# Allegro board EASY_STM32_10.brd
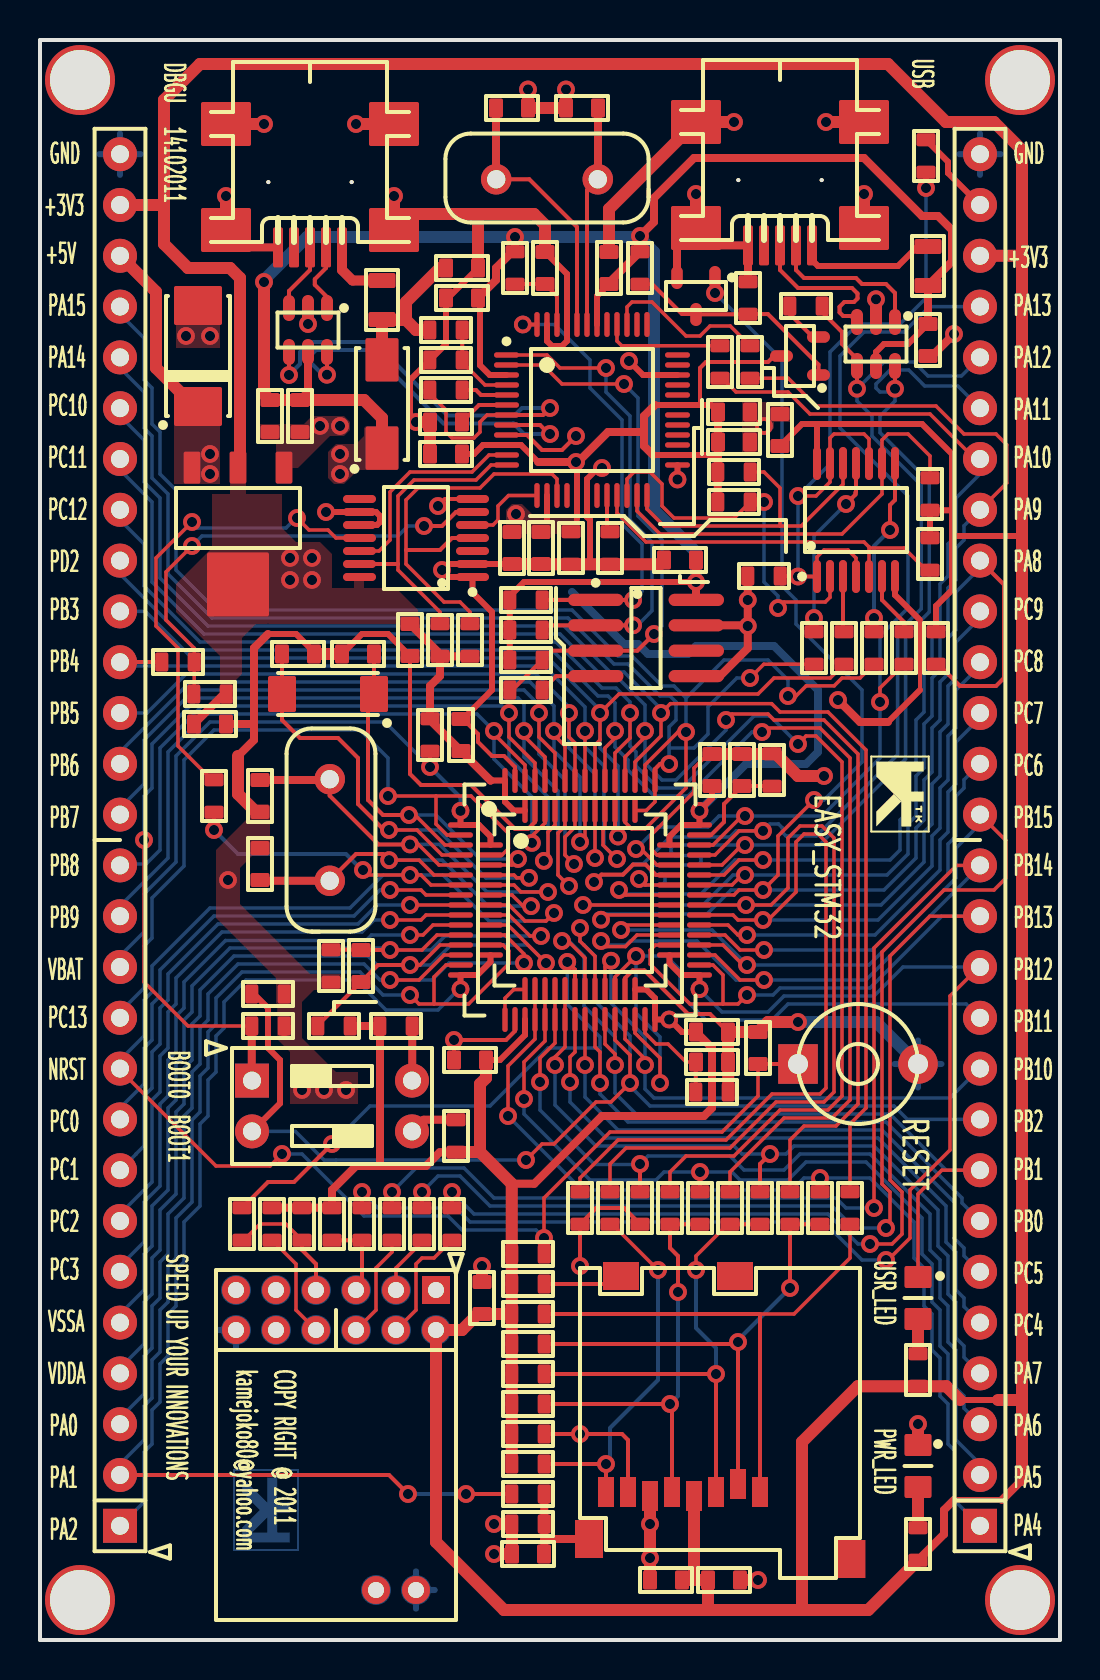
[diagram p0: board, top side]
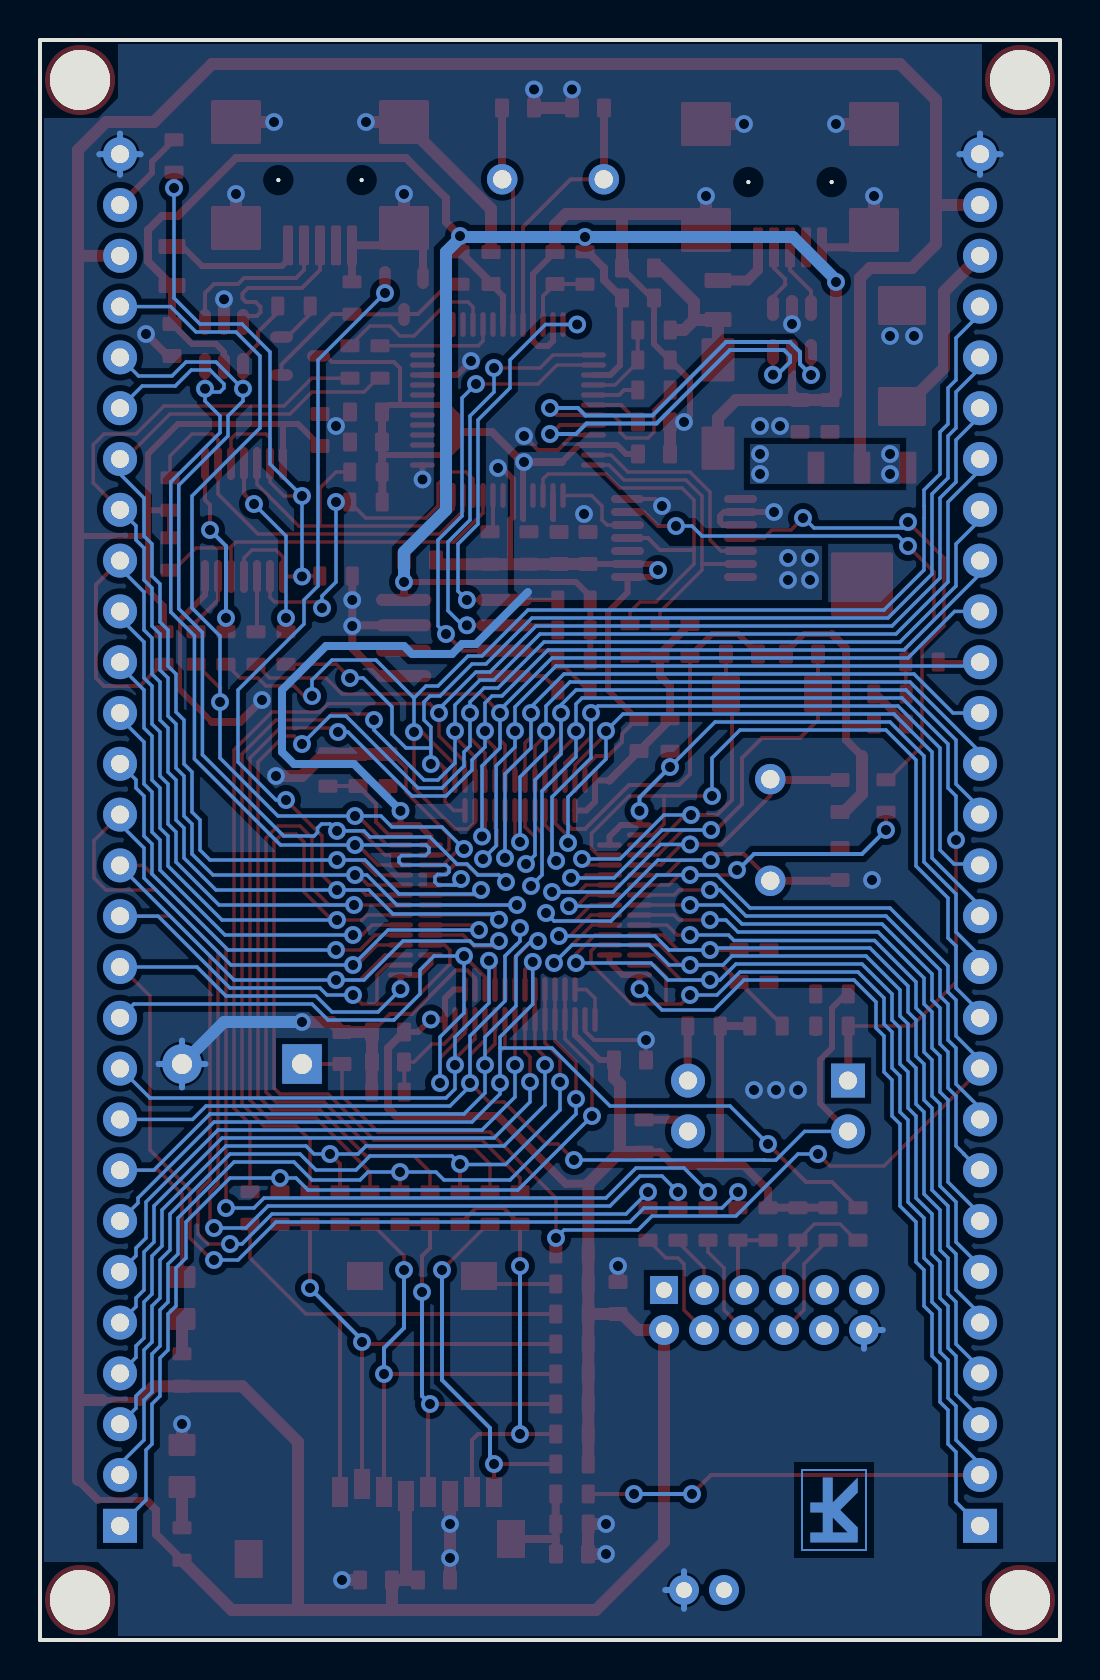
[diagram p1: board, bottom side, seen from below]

Outline 51 x 80 mm; copper layers: TOP, BOTTOM. Coordinates in mm from the lower left corner of the outline.
Outline path: 0,80 0,0 51,0 51,80 0,80

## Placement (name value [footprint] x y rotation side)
C1  22p  [CAP0603_B]  11 42.2 270 top
C2  22p  [CAP0603_B]  11 38.8 90 top
C3  15p  [CAP0603_B]  12.9 49.3 0 top
C4  15p  [CAP0603_B]  15.9 49.3 180 top
C5  100n  [CAP0603_B]  16.05 33.7 90 top
C6  100n  [CAP0603_B]  33.6 30.4 0 top
C7  100n  [CAP0603_B]  33.6 43.5 90 top
C8  100n  [CAP0603_B]  21.05 45.25 90 top
C9  100n  [CAP0603_B]  21.5 29 180 top
C10  10u  [CAP0603_B]  21.1 68.6 0 top
C11  100n  [CAP0603_B]  21.1 67.1 180 top
C12  100n  [CAP0603_B]  28.45 68.6 90 top
C13  10u  [CAP0603_B]  23.6 54.6 270 top
C14  100n  [CAP0603_B]  20.3 59.3 180 top
C15  100n  [CAP0603_B]  25.05 54.6 270 top
C16  100n  [CAP0603_B]  34.7 59.9 0 top
C17  100n  [CAP0603_B]  34.7 61.4 0 top
C18  100n  [CAP0603_B]  25.25 68.6 90 top
C19  100n  [CAP0603_B]  20.3 60.9 180 top
C20  22p  [CAP0603_B]  27.1 76.6 180 top
C21  22p  [CAP0603_B]  23.6 76.6 0 top
C22  100n  [CAP0603_B]  32 54 180 top
C23  220u  [CAP220UF]  7.9 64.2 90 top
C24  100n  [CAP0603_B]  11.5 61.2 270 top
C25  10u  [CAP0603_B]  8.5 45.8 0 top
C26  100n  [CAP0603_B]  44.4 65 270 top
C27  100n  [CAP0603_B]  33.6 28.9 0 top
C28  100n  [CAP0603_B]  35.1 43.5 90 top
C29  100n  [CAP0603_B]  13 61.2 270 top
C43  100n  [CAP0603_B]  31.3 3 180 top
C44  10u  [CAP0603_B]  34.2 3 0 top
C45  100n  [CAP0603_B]  37 60.5 90 top
C46  100n  [CAP0603_B]  18.5 50 270 top
C47  100n  [CAP0603_B]  24.4 4.3 180 top
C48  100n  [CAP0603_B]  35.9 29.6 90 top
C49  100n  [CAP0603_B]  22.1 17.1 90 top
D1  LED  [LEDC2012X120M]  43.9 8.7 270 top
D2  1N5819  [SS14]  17.1 61.8 90 top
D3  LED  [LEDC2012X120M]  43.9 17.1 270 top
J1  USB_MB  [HIROSE-US60-MB-5ST]  13.5 78.9 180 top
J2  USB_MB  [HIROSE-US60-MB-5ST]  37 79 180 top
J3  CON28  [CON28-1X28]  47 5.71 90 top
J4  CON28  [CON28-1X28]  4 5.71 90 top
L1  FB60R  [RES0805_B]  17.1 67 90 top
L2  FB60R  [RES0805_B]  44.4 68.7 90 top
NOREF  val  [unnamed]  49 78 0 top
NOREF#2  val  [unnamed]  2 78 0 top
NOREF#3  val  [unnamed]  49 2 0 top
NOREF#4  -  [#2]  51.55 -0.02 90 top
NOREF#5  val  [unnamed]  2 2 0 top
NOREF#6  -  [#2]  0.07 0.66 0 top
NOREF#7  -  [#2]  41.56 44.17 270 top
NOREF#8  -  [#2]  9.86 4.62 90 bottom
Q1  C1815  [SOT-23]  38 64.2 90 top
Q2  C1815  [SOT-23]  32.8 67.2 180 top
R1  0R  [RES0603_B]  19.5 45.25 90 top
R2  0R  [RES0603_B]  14.7 30.7 0 top
R3  0R  [RES0603_B]  14.55 33.7 270 top
R4  470R  [RES0603_B]  23.75 68.6 270 top
R5  4K7  [RES0603_B]  20.3 65.5 0 top
R6  10K  [RES0603_B]  20.3 64 180 top
R7  10K  [RES0603_B]  28.5 54.6 270 top
R8  10K  [RES0603_B]  24.3 49 0 top
R9  10K  [RES0603_B]  24.3 50.5 0 top
R10  10K  [RES0603_B]  24.3 52 0 top
R11  2K2  [RES0603_B]  24.3 47.5 0 top
R12  330R  [RES0603_B]  43.9 4.8 90 top
R13  1K5  [RES0603_B]  20.3 62.5 0 top
R14  100K  [RES0603_B]  26.55 54.6 270 top
R15  10K  [RES0603_B]  24.4 10.3 0 top
R16  10K  [RES0603_B]  24.4 13.3 0 top
R17  10K  [RES0603_B]  24.4 11.8 0 top
R18  10K  [RES0603_B]  24.4 14.8 0 top
R19  10K  [RES0603_B]  24.4 8.8 0 top
R20  10K  [RES0603_B]  24.4 16.3 0 top
R21  10K  [RES0603_B]  24.4 17.8 0 top
R22  1K  [RES0603_B]  24.4 5.8 180 top
R23  0R  [RES0603_B]  27 21.6 270 top
R24  0R  [RES0603_B]  34.5 21.6 270 top
R25  0R  [RES0603_B]  31.5 21.6 270 top
R26  0R  [RES0603_B]  37.5 21.6 270 top
R27  0R  [RES0603_B]  28.5 21.6 270 top
R28  0R  [RES0603_B]  40.5 21.6 270 top
R29  0R (DNP)  [RES0603_B]  30 21.6 90 top
R30  0R (DNP)  [RES0603_B]  36 21.6 90 top
R31  0R (DNP)  [RES0603_B]  33 21.6 90 top
R32  0R (DNP)  [RES0603_B]  39 21.6 90 top
R33  0R  [RES0603_B]  24.4 7.3 0 top
R34  39R  [RES0603_B]  34 63.9 270 top
R35  100R  [RES0603_B]  40.2 49.6 270 top
R36  100R  [RES0603_B]  43.2 49.6 270 top
R37  100R  [RES0603_B]  41.7 49.6 270 top
R38  100R  [RES0603_B]  38.7 49.6 270 top
R39  100K  [RES0603_B]  20 50 90 top
R40  100K  [RES0603_B]  21.5 50 90 top
R41  100R  [RES0603_B]  6.9 48.9 180 top
R42  100R  [RES0603_B]  8.7 42.2 270 top
R43  0R  [RES0603_B]  33.6 27.4 0 top
R44  10K  [RES0603_B]  30 68.6 270 top
R45  36K  [RES0603_B]  35.4 67.1 90 top
R46  1K5  [RES0603_B]  38.3 66.7 0 top
R47  47K  [RES0603_B]  44.8 49.6 270 top
R48  0R  [RES0603_B]  36.6 43.5 90 top
R49  10K  [RES0603_B]  24.4 19.3 0 top
R50  1K  [RES0603_B]  11.4 30.7 0 top
R51  1K  [RES0603_B]  11.4 32.3 0 top
R52  10K  [RES0603_B]  17.8 30.7 0 top
R53  10K  [RES0603_B]  20.8 25.2 90 top
R54  10K  [RES0603_B]  8.5 47.3 180 top
R55  10K  [RES0603_B]  34.7 56.9 0 top
R56  10K  [RES0603_B]  44.5 54.3 270 top
R57  10K  [RES0603_B]  44.5 57.3 90 top
R58  10K  [RES0603_B]  34.7 58.4 0 top
R59  39R  [RES0603_B]  35.5 63.9 270 top
R60  10K  [RES0603_B]  14.6 20.8 270 top
R61  0R  [RES0603_B]  16.1 20.8 270 top
R62  10K  [RES0603_B]  11.6 20.8 270 top
R63  10K  [RES0603_B]  13.1 20.8 270 top
R64  0R  [RES0603_B]  10.1 20.8 270 top
R65  0R  [RES0603_B]  19.1 20.8 270 top
R66  0R  [RES0603_B]  20.6 20.8 90 top
R67  0R  [RES0603_B]  17.6 20.8 90 top
R68  1K  [RES0603_B]  36.2 53.2 180 top
R69  10K  [RES0603_B]  44.3 74.2 270 top
R70  330R  [RES0603_B]  43.9 13.5 90 top
S1  BT  [BUTTON_RST_CIRCLE]  40.9 28.8 0 top
S2  SW DIP-2  [DIP_SWITCH_2]  14.6 26.7 270 top
U1  STM32F103RCT6  [LQFP64_MODIFIED]  27 37 0 top
U2  STM32F100  [LQFP48L_MODIFIED]  27 37 0 top
U3  FT2232D  [LQFP48L]  27.6 61.5 0 top
U4  AT93C46-10SI-2.7  [SOIC8S1JEDECM]  30.3 50.1 270 top
U5  74LVC125A  [TSOP65P640X120-14]  40.8 56 0 top
U6  74LVC125A  [TSOP65P640X120-14]  18.8 55.1 90 top
U7  LD1117-3V3  [SOT-223]  9.9 55.42 180 top
U8  RFM12  [RFM12-2X6]  19.8 17.5 180 top
U10  MICRO_SD  [MICRO_SD_PUSH]  41 18.6 180 top
U11  USBLC6-2P6  [SOT23-6L]  41.8 64.8 180 top
U12  USBLC6-2P6  [SOT23-6L]  13.4 65.5 180 top
Y1  8M  [XTAL_DIP]  14.49 37.96 90 top
Y2  32.768KHz  [ABS10]  14.4 47.3 180 top
Y3  6M  [XTAL_DIP]  27.89 73.04 180 top

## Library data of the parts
C1-C9 C24 C25 C27 C28 = C1005_0: User Part Number: pn; Tolerance: RichardLC
C10-C22 C26 C29 = CAP NP_0: User Part Number: pn; Tolerance: RichardLC
C23 = CAPACITOR POL: User Part Number: pn; Tolerance: RichardLC
C43-C49 = C1005_5: User Part Number: pn; Tolerance: RichardLC
D1 D3 = LED_0: User Part Number: pn; Tolerance: RichardLC
D2 = DIODE SCHOTTKY_1: User Part Number: pn; Tolerance: RichardLC
J1 J2 = CON9_2: User Part Number: pn; Tolerance: RichardLC
J3 J4 = CON26_0: User Part Number: pn; Tolerance: RichardLC
L1 L2 = INDUCTOR/SM_0: User Part Number: pn; Tolerance: RichardLC
NOREF NOREF#3 NOREF#5 = -: User Part Number: pn; Tolerance: RichardLC
NOREF#2 = -: Tolerance: RichardLC; User Part Number: pn
Q1 Q2 = 2N3904_0: User Part Number: pn; Tolerance: RichardLC
R1-R70 = R_0: User Part Number: pn; Tolerance: RichardLC
S1 = SW PUSHBUTTON_1: User Part Number: pn; Tolerance: RichardLC
S2 = SW DIP-2_1: User Part Number: pn; Tolerance: RichardLC
U1 = STM32F103RCT6_2: User Part Number: pn; Tolerance: RichardLC
U2 = STM32F100_1: User Part Number: pn; Tolerance: RichardLC
U3 = FT2232D_0: User Part Number: pn; Tolerance: RichardLC
U4 = 93C46_2: User Part Number: pn; Tolerance: RichardLC
U5 U6 = 74HC125/LCC_0: User Part Number: pn; Tolerance: RichardLC
U7 = LD1117: User Part Number: pn; Tolerance: RichardLC
U8 = RFM12: User Part Number: pn; Tolerance: RichardLC
U10 = MOLEX_uSD_0: User Part Number: pn; Tolerance: RichardLC
U11 U12 = USBLC6-2P6: User Part Number: pn; Tolerance: RichardLC
Y1 Y3 = ZTB: Tolerance: ***; User Part Number: ***
Y2 = ZTA: User Part Number: pn; Tolerance: RichardLC

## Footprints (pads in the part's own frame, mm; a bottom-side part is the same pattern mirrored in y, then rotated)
ABS10
  custom 0.35x0.35 smd: 1(-2.3,0) 2(2.3,0)
BUTTON_RST_CIRCLE
  rect 1.98x1.98 hole 1: 1(-3,0)
  round 1.98 hole 1: 2(3,0)
CAP220UF
  custom 0.487x0.487 smd: 1(-2.525,0) 2(2.525,0)
CAP0603_B
  custom 0.175x0.175 smd: 1(-0.8,0) 2(0.8,0)
CON28-1X28
  rect 1.7x1.7 hole 0.9: 1(0,0)
  round 1.7 hole 0.9: 2(2.54,0) 3(5.08,0) 4(7.62,0) 5(10.16,0) 6(12.7,0) 7(15.24,0) 8(17.78,0) 9(20.32,0) 10(22.86,0) 11(25.4,0) 12(27.94,0) 13(30.48,0) 14(33.02,0) 15(35.56,0) 16(38.1,0) 17(40.64,0) 18(43.18,0) 19(45.72,0) 20(48.26,0) 21(50.8,0) 22(53.34,0) 23(55.88,0) 24(58.42,0) 25(60.96,0) 26(63.5,0) 27(66.04,0) 28(68.58,0)
DIP_SWITCH_2
  rect 1.7x1.7 hole 0.9: 1(-1.27,-4)
  round 1.7 hole 0.9: 2(1.27,-4) 3(1.27,4) 4(-1.27,4)
HIROSE-US60-MB-5ST
  round 0.2 hole 0.9 unplated: (-2.083,6.005) (2.083,6.005)
  custom 0.125x0.125 smd: 1(-1.6,9.271) 2(-0.8,9.271) 3(0,9.271) 4(0.8,9.271) 5(1.6,9.271)
  custom 0.55x0.55 smd: 6(-4.2,3.1) 7(4.2,3.1) 8(-4.2,8.4) 9(4.2,8.4)
LEDC2012X120M
  custom 0.275x0.275 smd: A(1.05,0) C(-1.05,0)
LQFP48L
  oval 1.25x0.27 smd: 1(-4.275,2.75) 2(-4.275,2.25) 3(-4.275,1.75) 4(-4.275,1.25) 5(-4.275,0.75) 6(-4.275,0.25) 7(-4.275,-0.25) 8(-4.275,-0.75) 9(-4.275,-1.25) 10(-4.275,-1.75) 11(-4.275,-2.25) 12(-4.275,-2.75) 25(4.275,-2.75) 26(4.275,-2.25) 27(4.275,-1.75) 28(4.275,-1.25) 29(4.275,-0.75) 30(4.275,-0.25) 31(4.275,0.25) 32(4.275,0.75) 33(4.275,1.25) 34(4.275,1.75) 35(4.275,2.25) 36(4.275,2.75)
  oval 0.27x1.25 smd: 13(-2.75,-4.275) 14(-2.25,-4.275) 15(-1.75,-4.275) 16(-1.25,-4.275) 17(-0.75,-4.275) 18(-0.25,-4.275) 19(0.25,-4.275) 20(0.75,-4.275) 21(1.25,-4.275) 22(1.75,-4.275) 23(2.25,-4.275) 24(2.75,-4.275) 37(2.75,4.275) 38(2.25,4.275) 39(1.75,4.275) 40(1.25,4.275) 41(0.75,4.275) 42(0.25,4.275) 43(-0.25,4.275) 44(-0.75,4.275) 45(-1.25,4.275) 46(-1.75,4.275) 47(-2.25,4.275) 48(-2.75,4.275)
LQFP48L_MODIFIED
  oval 1.25x0.27 smd: 1(-4.475,2.75) 2(-4.475,2.25) 3(-4.475,1.75) 4(-4.475,1.25) 5(-4.475,0.75) 6(-4.475,0.25) 7(-4.475,-0.25) 8(-4.475,-0.75) 9(-4.475,-1.25) 10(-4.475,-1.75) 11(-4.475,-2.25) 12(-4.475,-2.75) 25(4.475,-2.75) 26(4.475,-2.25) 27(4.475,-1.75) 28(4.475,-1.25) 29(4.475,-0.75) 30(4.475,-0.25) 31(4.475,0.25) 32(4.475,0.75) 33(4.475,1.25) 34(4.475,1.75) 35(4.475,2.25) 36(4.475,2.75)
  oval 0.27x1.25 smd: 13(-2.75,-4.475) 14(-2.25,-4.475) 15(-1.75,-4.475) 16(-1.25,-4.475) 17(-0.75,-4.475) 18(-0.25,-4.475) 19(0.25,-4.475) 20(0.75,-4.475) 21(1.25,-4.475) 22(1.75,-4.475) 23(2.25,-4.475) 24(2.75,-4.475) 37(2.75,4.475) 38(2.25,4.475) 39(1.75,4.475) 40(1.25,4.475) 41(0.75,4.475) 42(0.25,4.475) 43(-0.25,4.475) 44(-0.75,4.475) 45(-1.25,4.475) 46(-1.75,4.475) 47(-2.25,4.475) 48(-2.75,4.475)
LQFP64_MODIFIED
  oval 1.25x0.27 smd: 1(-5.975,3.75) 2(-5.975,3.25) 3(-5.975,2.75) 4(-5.975,2.25) 5(-5.975,1.75) 6(-5.975,1.25) 7(-5.975,0.75) 8(-5.975,0.25) 9(-5.975,-0.25) 10(-5.975,-0.75) 11(-5.975,-1.25) 12(-5.975,-1.75) 13(-5.975,-2.25) 14(-5.975,-2.75) 15(-5.975,-3.25) 16(-5.975,-3.75) 33(5.975,-3.75) 34(5.975,-3.25) 35(5.975,-2.75) 36(5.975,-2.25) 37(5.975,-1.75) 38(5.975,-1.25) 39(5.975,-0.75) 40(5.975,-0.25) 41(5.975,0.25) 42(5.975,0.75) 43(5.975,1.25) 44(5.975,1.75) 45(5.975,2.25) 46(5.975,2.75) 47(5.975,3.25) 48(5.975,3.75)
  oval 0.27x1.25 smd: 17(-3.75,-5.975) 18(-3.25,-5.975) 19(-2.75,-5.975) 20(-2.25,-5.975) 21(-1.75,-5.975) 22(-1.25,-5.975) 23(-0.75,-5.975) 24(-0.25,-5.975) 25(0.25,-5.975) 26(0.75,-5.975) 27(1.25,-5.975) 28(1.75,-5.975) 29(2.25,-5.975) 30(2.75,-5.975) 31(3.25,-5.975) 32(3.75,-5.975) 49(3.75,5.975) 50(3.25,5.975) 51(2.75,5.975) 52(2.25,5.975) 53(1.75,5.975) 54(1.25,5.975) 55(0.75,5.975) 56(0.25,5.975) 57(-0.25,5.975) 58(-0.75,5.975) 59(-1.25,5.975) 60(-1.75,5.975) 61(-2.25,5.975) 62(-2.75,5.975) 63(-3.25,5.975) 64(-3.75,5.975)
MICRO_SD_PUSH
  rect 0.8x1.5 smd: 1(5,11.2) 2(6.1,10.8) 3(7.2,11.2) 4(8.3,11.4) 5(9.4,11.2) 6(10.5,11.4) 7(11.6,11.2) 8(12.7,11.2)
  rect 1.4x1.9 smd: G1(0.43,14.55) G2(13.55,13.55)
  rect 1.8x1.4 smd: S1(6.25,0.4) S2(11.95,0.4)
RES0603_B
  custom 0.163x0.163 smd: 1(-0.812,0) 2(0.812,0)
RES0805_B
  custom 0.188x0.188 smd: 1(-0.975,0) 2(0.975,0)
RFM12-2X6
  rect 1.4x1.4 hole 0.8: 1(0,0)
  round 1.4 hole 0.8: 2(0,2) 3(2,0) 4(2,2) 5(4,0) 6(4,2) 7(6,0) 8(6,2) 9(8,0) 10(8,2) 11(10,0) 12(10,2) 13(1,15) 14(3,15)
SOIC8S1JEDECM
  oval 0.61x2.77 smd: 1(-1.905,-2.515) 2(-0.635,-2.515) 3(0.635,-2.515) 4(1.905,-2.515) 5(1.905,2.515) 6(0.635,2.515) 7(-0.635,2.515) 8(-1.905,2.515)
SOT23-6L
  oval 0.6x1.3 smd: 1(-0.95,-1.1) 2(0,-1.1) 3(0.95,-1.1) 4(0.95,1.1) 5(0,1.1) 6(-0.95,1.1)
SOT-23
  oval 0.58x1.15 smd: 1(-0.95,-0.925) 2(0.95,-0.925) 3(0,0.925)
SOT-223
  custom 0.21x0.21 smd: 1(-2.3,-3.195) 2(0,-3.195) 3(2.3,-3.195)
  custom 0.775x0.775 smd: 4(0,2.645)
SS14
  custom 0.412x0.412 smd: A(2.21,0) C(-2.21,0)
TSOP65P640X120-14
  oval 0.4x1.65 smd: 1(-1.95,-2.825) 2(-1.3,-2.825) 3(-0.65,-2.825) 4(0,-2.825) 5(0.65,-2.825) 6(1.3,-2.825) 7(1.95,-2.825) 8(1.95,2.825) 9(1.3,2.825) 10(0.65,2.825) 11(0,2.825) 12(-0.65,2.825) 13(-1.3,2.825) 14(-1.95,2.825)
unnamed
  round 3.5 hole 3: 1(0,0)
XTAL_DIP
  round 1.524 hole 0.914: 1(0,0) 2(5.08,0)

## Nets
+3V3: C6.1 C7.1 C8.1 C9.1 C13.1 C14.1 C15.1 C16.1 C17.1 C25.1 C43.1 C44.1 C45.1 C46.1 C49.1 J3.26 J4.27 Q1.3(C) R1.2 R2.2 R12.1 R14.1 R15.1 R16.1 R17.1 R18.1 R19.1 R20.1 R21.1 R39.1 R40.1 R47.1 R49.1 R52.1 R53.1 R54.1 R55.1 R56.1 R57.1 R58.1 R60.1 R62.1 R63.1 R70.1 U1.19(VDD_4) U1.32(VDD_1) U1.48(VDD_2) U1.64(VDD_3) U2.24(VDD_1) U2.36(VDD_2) U2.48(VDD_3) U3.10(SI/WUA) U3.14(VCCIOA) U3.17(ADBUS6) U3.26(SI/WUB) U3.31(VCCIOB) U5.14(VCC) U6.14(VCC) U7.2(VOUT) U7.4(SH) U8.2(VDD) U10.4(VDD)
+5V: C11.1 C12.1 C22.1 C23.1 C24.1 C26.1 C29.1 D2.C J4.26 L2.1 R4.1 R8.1 R9.1 R10.1 R44.1 U3.3(VCC1) U3.42(VCC2) U4.8(VCC) U7.3(VIN) U11.5(VBUS) U12.5(VBUS)
GND: C1.2 C2.2 C3.2 C4.2 C6.2 C7.2 C8.2 C9.2 C10.2 C11.2 C12.2 C13.2 C14.2 C15.2 C16.2 C17.2 C18.2 C19.2 C20.2 C21.2 C22.2 C23.2 C24.2 C25.2 C26.2 C27.2 C28.2 C29.2 C43.2 C44.2 C45.2 C46.2 C47.2 C48.2 C49.2 D1.C J1.5(GND) J1.6(SH1) J1.7(SH2) J1.8(SH3) J1.9(SH4) J2.5(GND) J2.6(SH1) J2.7(SH2) J2.8(SH3) J2.9(SH4) J3.28 J4.28 Q2.2(E) R3.2 R6.2 R7.2 R14.2 R22.2 R43.2 R45.2 R48.2 R50.2 R51.2 R68.2 S1.2 U1.18(VSS_4) U1.63(VSS_3) U2.23(VSS_1) U2.35(VSS_2) U2.47(VSS_3) U3.9(GND1) U3.18(GND2) U3.25(GND3) U3.34(GND4) U3.45(AGND) U3.47(TEST) U4.5(GND) U4.7(NC) U5.7(GND) U6.1(O\E\1\) U6.2(A1) U6.7(GND) U6.9(A3) U6.10(O\E\3\) U7.1(GND) U8.12(GND1) U8.13(GND2) U10.6(VSS) U11.2(GND) U12.2(GND)
VBAT: J4.12 R1.1 U1.1(VBAT) U2.1(VBAT)
VDDA: C5.1 J4.4 R2.1 U1.13(VDDA) U2.9(VDDA)
VSSA: C5.2 J4.5 R3.1 U1.12(VSSA) U2.8(VSSA)
BOOT0: R50.1 S2.1 U1.60(BOOT0) U2.44(BOOT0)
EECK: R9.2 U3.1(EESK) U4.2(CLK)
EECS: R10.2 U3.48(EECS) U4.1(CS)
EEDA: R8.2 R11.1 U3.2(EEDATA) U4.3(DI)
JT_SRSTN: U3.16(ADBUS7)
JTAG_SELN: J3.27 R69.1
NRST: C48.1 J4.10 R42.2 R49.2 S1.1 U1.7(NRST) U2.7(NRST)
OSC32_IN: C4.1 U1.3(PC14/OSC32_IN) U2.3(PC14/OSC32_IN) Y2.1
OSC32_OUT: C3.1 U1.4(PC15/OSC32/OUT) U2.4(PC15/OSC32_OUT) Y2.2
OSC_IN: C1.1 U1.5(PD0/OSC_IN) U2.5(PD0/OSC_IN) Y1.2
OSC_OUT: C2.1 U1.6(PD1/OSC_OUT) U2.6(PD1/OSC_OUT) Y1.1
PA0: J4.3 U1.14(PA0-WKUP) U2.10(PA0/WKUP)
PA1: J4.2 R33.1 U1.15(PA1) U2.11(PA1)
PA2: J4.1 U1.16(PA2) U2.12(PA2)
PA3: U1.17(PA3) U2.13(PA3)
PA4: J3.1 R32.2 U1.20(PA4) U2.14(PA4)
PA5: J3.2 R31.2 U1.21(PA5) U2.15(PA5)
PA6: J3.3 R29.2 U1.22(PA6) U2.16(PA6)
PA7: J3.4 R30.2 U1.23(PA7) U2.17(PA7)
PA8: J3.20 Q2.1(B) R47.2 U1.41(PA8) U2.29(PA8)
PA9: J3.21 R59.2 U1.42(PA9) U2.30(PA9)
PA10: J3.22 R34.2 U1.43(PA10) U2.31(PA10)
PA11: J3.23 U1.44(PA11) U2.32(PA11) U11.6(IO1_2)
PA12: J3.24 R46.2 U1.45(PA12) U2.33(PA12) U11.4(IO2_2)
PA13: J3.25 R36.2 U1.46(PA13) U2.34(PA13)
PA14: J4.24 R38.2 U1.49(PA14) U2.37(PA14)
PA15: J4.25 R37.2 U1.50(PA15) U2.38(PA15)
PB0: J3.7 R64.1 U1.26(PB0) U2.18(PB0)
PB1: D3.C J3.8 U1.27(PB1) U2.19(PB1)
PB2: J3.9 R51.1 S2.2 U1.28(PB2/BOOT1) U2.20(PB2)
PB3: J4.19 R35.2 U1.55(PB3) U2.39(PB3)
PB4: J4.18 R41.2 U1.56(PB4) U2.40(PB4)
PB5: J4.17 U1.57(PB5) U2.41(PB5)
PB6: J4.16 U1.58(PB6) U2.42(PB6)
PB7: J4.15 U1.59(PB7) U2.43(PB7)
PB8: J4.14 U1.61(PB8) U2.45(PB8)
PB9: J4.13 U1.62(PB9) U2.46(PB9)
PB10: J3.10 U1.29(PB10) U2.21(PB10)
PB11: J3.11 U1.30(PB11) U2.22(PB11)
PB12: J3.12 R61.1 U1.33(PB12) U2.25(PB12)
PB13: J3.13 R66.2 U1.34(PB13) U2.26(PB13)
PB14: J3.14 R67.2 U1.35(PB14) U2.27(PB14)
PB15: J3.15 R65.1 U1.36(PB15) U2.28(PB15)
PC0: J4.9 U1.8(PC0)
PC1: J4.8 U1.9(PC1)
PC2: J4.7 U1.10(PC2)
PC3: J4.6 U1.11(PC3)
PC4: J3.5 U1.24(PC4)
PC5: J3.6 U1.25(PC5)
PC6: J3.16 U1.37(PC6)
PC7: J3.17 U1.38(PC7)
PC8: J3.18 R23.1 U1.39(PC8)
PC9: J3.19 R27.1 U1.40(PC9)
PC10: J4.23 R28.1 U1.51(PC10)
PC11: J4.22 R26.1 U1.52(PC11)
PC12: J4.21 R25.1 U1.53(PC12)
PC13: J4.11 U1.2(PC13/TAMPER/RTC) U2.2(PC13/TAMPER/RTC)
PD2: J4.20 R24.1 U1.54(PD2)
RXD: R59.1 U3.39(BDBUS1)
SRST: U3.11(ACBUS3) U6.12(A4)
SRST_OE: R39.2 U3.12(ACBUS2) U6.13(O\E\4\)
TRST: U3.13(ACBUS1) U6.5(A2)
TRST_OE: R40.2 U3.15(ACBUS0) U6.4(O\E\2\)
TXD: R34.1 U3.40(BDBUS0)
USB_CLK: R58.2 U3.24(ADBUS0) U5.12(A4)
USB_TDI: R57.2 U3.23(ADBUS1) U5.9(A3)
USB_TDO: R55.2 U3.22(ADBUS2) U5.2(A1)
USB_TMS: R56.2 U3.21(ADBUS3) U5.5(A2)
N50123: R13.1 U3.7(USBDP) U12.4(IO2_2)
N50127: C18.1 R4.2 U3.46(AVCC)
N50535: R7.1 U3.20(ADBUS4)
N50793: C20.1 U3.43(XTIN) Y3.1
N50801: C21.1 U3.44(XTOUT) Y3.2
N51029: C10.1 D2.A L1.1 R5.1
N51243: J1.1(VBUS) L1.2
N51319: R13.2 U3.5(R\S\T\O\U\T\)
N51343: U3.8(USBDM) U12.6(IO1_2)
N51347: R5.2 R6.1 U3.4(R\E\S\E\T\)
N51363: C19.1 U3.6(3V3OUT)
N51511: R11.2 U4.4(DO)
N51727: D1.A R12.2
N70187: R15.2 R23.2 R29.1 U10.7(DAT0/DO)
N70219: R17.2 R25.2 R31.1 U10.5(CLK)
N70227: R18.2 R26.2 R32.1 U10.2(CD/C\S\/DAT3)
N70305: R21.2 U10.S2
N70345: C47.1 R22.1 R33.2 U10.G2
N70603: R19.2 R27.2 U10.8(DAT1/RSV)
N14914218: R16.2 R24.2 R30.1 U10.3(CMD/DI)
N14919452: R35.1 U5.3(Y1)
N14919456: R36.1 U5.6(Y2)
N14919460: R37.1 U5.8(Y3)
N14919464: R38.1 U5.11(Y4)
N14919484: R68.1 R69.2 U5.1(O\E\1\) U5.4(O\E\2\) U5.10(O\E\3\) U5.13(O\E\4\)
N14919761: R20.2 R28.2 U10.1(DAT2/NC)
N14928576: R41.1 R54.2 U6.6(Y2)
N14928580: R42.1 U6.11(Y4)
N14948550: J2.1(VBUS) L2.2
N14948554: J2.2(DM) U11.1(IO1_1)
N14948558: J2.3(DP) U11.3(IO2_1)
N14952468: Q1.2(E) R46.1
N14953185: Q1.1(B) Q2.3(C) R44.2 R45.1
N14959571: J1.3(DP) U12.3(IO2_1)
N14961045: J1.2(DM) U12.1(IO1_1)
N14964930: C27.1 R43.1 U1.31(VSS_1)
N14964937: C28.1 R48.1 U1.47(VSS_2)
N14983071: R52.2 S2.4
N14983075: R53.2 S2.3
N14990127: R62.2 U8.8(FSK/DATA/NFFS)
N14990147: R66.1 U8.4(SCK)
N14990153: R67.1 U8.6(SDO)
N14990191: R65.2 U8.3(SDI)
N14990197: R60.2 R61.2 U8.5(NSEL)
N14990201: R63.2 R64.2 U8.7(NIR0)
N15001570: D3.A R70.2

Pads without a net: J1 4; J2 4; NOREF 1; NOREF#2 1; NOREF#3 1; NOREF#5 1; U3 19 27 28 29 30 32 33 35 36 37 38 41; U4 6; U6 3 8; U8 1 9 10 11 14; U10 G1 S1

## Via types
v1: diameter 0.889, hole 0.508, TOP to BOTTOM, 208 vias

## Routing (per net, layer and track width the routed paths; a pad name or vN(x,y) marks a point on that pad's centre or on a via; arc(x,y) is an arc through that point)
+3V3: length 386.6
  TOP w0.2: 49.09,69.21 49.1,69.2 ; 33,61.75 33,63.6 33.3,63.9 36.4,63.9 36.7,64.2 Q1.3 ; 26.8,56 26.85,56.05 ; 25.3,56 25.35,56.05 ; 45.59,56.49 45.6,56.5
  TOP w0.3: 26.9,58.9 v1(26.8,58.9) 26.85,58.85 U3.17 26.85,56.05 ; U2.36 31.48,40.17 32.05,40.75 U1.48 v1(32.98,41.46) 32.98,41.48 33.6,42.1 C7.1 ; C14.1 21.7,59.3 22.15,59.75 U3.10 24.05,59.75 24.9,58.9 ; U2.24 30.32,32.52 30.57,32.27 30.75,32.09 U1.32 v1(31.46,31.02) 31.48,31.02 32.1,30.4 C6.1 ; 49.1,55.2 45.6,55.2 ; 45.6,55.2 45.6,59.3 44.1,60.8 38.8,60.8 ; 45.6,55.2 45.6,52.5 44.8,51.7 R47.1 ; C9.1 23,29 24.25,30.25 U1.19 ; 38.8,60.8 38.1,60.8 C45.1 ; 38.8,60.8 38.85,60.75 U5.14 ; 25.35,56.05 U3.14 ; 30.75,61.75 U3.31 33.55,61.75 C17.1 ; 45.59,56.49 R57.1 R56.1 ; 30.65,59.25 U3.26 33.85,59.25 33.9,59.3 ; U2.48 23.69,41.48 23.25,41.91 U1.64 22.54,42.98 ; 48.1,7 45.7,7 ; 33.9,58.41 R58.1 ; 46,12 47.9,12
  TOP w0.4: 30.2,60.4 30.2,59.7 30.65,59.25 ; 30.2,60.4 30.2,61.2 30.75,61.75 ; 30.2,60.4 28.4,60.4 26.9,58.9 ; R12.1 45.2,5.29 45.2,6.5 45.7,7 ; R62.1 R63.1 R60.1 14.6,22.5 15.8,23.7 17,23.7 ; R40.1 R39.1 ; R39.1 20,48.2 19.5,47.7 R1.2 19.5,46 C8.1 22.52,42.98 22.54,42.98 ; R39.1 20,49.3 C46.1 ; 33.9,58.41 C16.1 C17.1 ; 49.1,8 48.1,7 ; C25.1 9.2,47.3 R54.1 ; 17,23.7 19.3,23.7 19.99,24.39 R53.1 ; 17,23.7 17,30.69 R52.1 R2.2 ; R58.1 R55.1 ; C6.1 33.6,29.6 33.6,26.6 33.2,26.2 28.1,26.2 24.71,22.81 23.59,22.81 ; 24.9,58.9 v1(26.8,58.9)
  TOP w0.6: 47.9,12 49.1,12 ; 49.1,12 49.1,74.5 47.7,75.9 45.3,75.9 42.4,78.8 8,78.8 6.2,77 6.2,71.7 ; 49.1,12 49.1,8 ; R20.1 R21.1 R49.1 23.59,22.81 22,24.4 ; R20.1 C49.1 21.9,16.3 21.1,15.5 U8.2 19.8,4.9 23.2,1.5 33.4,1.5 ; R20.1 R18.1 R16.1 R17.1 R15.1 R19.1 ; R12.1 41.41,1.5 38.1,1.5 ; C9.1 22.3,28.1 22,27.8 22,24.4 ; C43.1 32.7,3 ; 32.7,3 U10.4 ; 32.7,3 C44.1 33.4,1.5 ; 22,24.4 20.81,24.4 R53.1 ; 33.4,1.5 38.1,1.5 ; 46,12 45.31,12.69 R70.1 40.89,12.69 38.1,9.9 38.1,1.5 ; 6.2,71.7 6.15,71.75 J4.27 ; 6.2,71.7 6.2,69.8 7.4,68.6 9.5,68.6 10,68.1 10,58.72 U7.2 ; J3.26 49.09,69.21
  BOTTOM w0.4: 26.6,52.4 29.2,49.8 29.9,49.8 30.4,49.3 32.4,49.3 32.8,49.7 36.7,49.7 38.9,47.5 38.9,44.4 38.3,43.8 35.3,43.8 32.98,41.48 v1(32.98,41.46)
  vias: v1(12.5,54.1) v1(12.5,53) v1(13.6,54.1) v1(13.6,53) v1(23.8,56.3)
+5V: length 121
  TOP w0.2: C23.1 7.73,61.67
  TOP w0.3: C11.1 22,67 22,63.73 22.48,63.25 U3.3 ; v1(32.8,52.9) 24.2,52.9 23.49,52.19 R10.1 R9.1 R8.1 ; U3.42 27.85,67.2 C12.1 ; U11.5 41.8,64.4 42.2,64.8 43.4,64.8 C26.1
  TOP w0.4: C12.1 28.45,67.86 R44.1 ; 32.81,52.01 32.8,52.02 v1(32.8,52.9) C22.1 ; C11.1 22.8,68 22.8,68.6 23.61,69.41 R4.1 v1(23.75,70.15) ; v1(30,70.2) 30.7,70.9 30.7,72.1 32.7,74.1 41.2,74.1 44.1,71.2 44.9,71.2 45.6,70.5 45.6,68.92 L2.1 C26.1 ; C29.1 13.4,62.4 U12.5
  TOP w0.6: D2.C 17.1,61.1 16.2,62 C29.1 C24.1 11.2,62.3 v1(11.2,67.9) ; 7.73,61.67 5.8,63.6 5.8,67.41 J4.26 ; R44.1 v1(30,70.2)
  BOTTOM w0.2: 29.95,70.15 v1(30,70.2)
  BOTTOM w0.6: v1(32.8,52.9) 32.8,54.4 30.7,56.5 30.7,69.4 29.95,70.15 v1(23.75,70.15) 13.35,70.15 11.2,68 v1(11.2,67.9)
  vias: v1(8.5,59.3) v1(8.5,58.3) v1(15,59.3) v1(15,58.3)
GND: length 237.5
  TOP w0.175: C7.2 33.4,44.3 32.7,43.6 32.7,42.4 30.55,40.25 30.55,39.55 30.85,39.25 U2.35
  TOP w0.2: 44,51 44,47.5 ; U1.63 23.75,43.65 23.2,44.2 22.6,44.2 21.9,44.9 21.9,45.3 21.15,46.05 C8.2 ; U3.9 24.35,60.25 25.1,59.5 26.1,59.5 v1(26.8,60.2) ; C9.2 v1(20.7,30) 23.3,30 23.75,30.45 U1.18 ; v1(19.9,56.7) 20.25,57.05 21.62,57.05 ; C6.2 33.5,31.3 32.4,31.3 30.22,33.48 29.63,33.48 29.25,33.09 U2.23 ; U2.47 24.75,40.9 24.4,40.55 23.75,40.55 21.55,42.75 19.05,42.75 18.5,43.3 C46.2 ; 23.6,5.79 R22.2
  TOP w0.3: U3.25 v1(31.88,58.02) ; C10.2 20.4,67.1 C11.2 20.3,64.8 19.5,64 R6.2 19.49,63.99 18.5,63 18.5,61.2 v1(18.8,60.9) ; C4.2 16.1,50.3 17.4,50.3 C46.2 ; C13.2 20.4,53.8 v1(20.1,53.5) 20.45,53.15 21.62,53.15 21.62,52.38 22.6,51.4 22.6,47.5 21.15,46.05 ; 11.4,50.3 12.8,50.3 13.7,49.4 C3.2 ; v1(14.3,56.4) U6.9 16.8,56.4 17,56.2 17,55.9 16.85,55.75 U6.10 ; 44,51 42.75,52.25 U5.7 ; U3.47 25.35,64.95 25.6,64.7 26.1,64.7 26.35,64.95 U3.45 26.35,68.3 C18.2 ; v1(28.1,58.6) 27.9,58.6 27.35,58.05 U3.18 27.35,56.15 27.5,56 27.5,53.79 ; v1(29.45,63.95) 30.15,63.25 U3.34 ; 44,47.5 42.4,45.9
  TOP w0.4: C25.2 10.7,45.8 ; 10.7,45.8 10.7,49.6 11.4,50.3 ; 10.7,45.8 10.7,45 9.9,44.2 ; 32.81,50.73 35.35,50.73 v1(35.39,50.7) ; v1(35.39,50.7) v1(35.39,52) R68.2 ; v1(35.39,50.7) 35.39,49.59 33.99,48.2 32.81,48.2 ; J1.5 10.17,69.63 J1.9 ; R45.2 J2.5 33.67,69.73 J2.9 31.85,69.65 Q2.2 ; v1(39.9,47) 41,45.9 42.4,45.9 ; v1(45.7,65.3) 44.6,64.2 C26.2
  TOP w0.6: C43.2 v1(30.5,4.1) v1(30.5,5.8) U10.6 ; U11.2 v1(41.8,67.04) ; J2.6 v1(39.3,75.9) ; 9.9,44.2 9.9,42.3 10.8,41.4 C1.2 ; C12.2 28.45,71.55 J2.7 v1(34.7,75.9) ; C7.2 C28.2 36.59,44.3 R48.2 36.79,44.31 37.9,43.2 v1(39.2,43.2) ; J1.9 v1(9.3,72.2) ; 21.9,71.3 18.5,71.3 J1.8 v1(17.7,72.2) ; 21.9,71.3 C10.2 ; 21.9,71.3 24.7,71.3 25.25,70.75 C18.2 ; v1(18.8,60.9) C19.2 C14.2 ; v1(26.3,77.53) C20.2 C21.2 v1(24.4,77.53) ; U12.2 v1(13.4,65.8) ; D1.C v1(43.9,10.8) ; C22.2 30.99,53.79 R7.2 R14.2 25.06,53.79 C15.2 C13.2 ; J1.6 v1(15.8,75.8) ; v1(37.9,30.9) 36.4,30.9 C48.2 C6.2 C27.2 34.41,28.89 R43.2 ; 12.21,30.49 R50.2 ; J2.8 v1(41.2,72.3) ; J2.9 v1(32.8,72.3) ; C49.2 v1(22.1,18.7) ; J1.7 v1(11.2,75.8) ; v1(22.7,4.3) C47.2 23.6,5.79 ; C3.2 C4.2 ; R22.2 v1(22.7,5.8) ; C44.2 v1(35.9,3)
  BOTTOM w0.305: U8.13 18.8,3.43 ; U8.13 19.73,2.5 ; U8.13 18.8,1.57 ; 4,73.26 J4.28 ; J4.28 2.97,74.29 ; J4.28 5.03,74.29 ; J4.28 4,75.32 ; S1.2 43.9,29.97 ; S1.2 45.07,28.8 ; S1.2 43.9,27.63 ; S1.2 42.73,28.8 ; 45.97,74.29 J3.28 ; J3.28 47,73.26 ; J3.28 47,75.32 ; J3.28 48.03,74.29 ; 8.87,15.5 U8.12 9.8,14.57
  BOTTOM w0.6: v1(37.9,30.9) 41.8,30.9 S1.2
  vias: v1(7.3,65.2) v1(8.5,65.2) v1(9.4,38) v1(13.1,27.5) v1(14,60.7) v1(14.2,27.5) v1(15,60.7) v1(15.3,27.5) v1(36.2,60.7)
VBAT: length 32.5
  TOP w0.2: R1.1 v1(19.5,43.65)
  TOP w0.3: U2.1 22.52,40.17 21.95,40.75 U1.1 v1(21.02,41.46)
  BOTTOM w0.175: J4.12 4,34.2 5.2,35.4 5.2,37.3 6.8,38.9 6.8,44.2 8.5,45.9 17.25,45.9 v1(19.5,43.65)
  BOTTOM w0.2: v1(19.5,43.65) 21.02,42.12 v1(21.02,41.46)
VDDA: length 52.2
  TOP w0.175: v1(18.5,33.75) 19,33.75 20,34.75 U1.13 ; U2.9 23.4,35.75 v1(25.3,33.85)
  TOP w0.2: R2.1 13.89,30.74 C5.1 16.9,33.75 v1(18.5,33.75)
  BOTTOM w0.175: J4.4 4,13.6 5.2,14.8 5.2,16.9 5.6,17.3 5.6,19.1 6,19.5 6,21.5 6.8,22.3 6.8,26.4 7.2,26.8 7.2,28.6 7.6,29 7.6,30.8 8,31.2 8,32.5 9.7,34.2 16.4,34.2 16.85,33.75 v1(18.5,33.75) 19.55,33.75 20.55,34.75 24.4,34.75 v1(25.3,33.85)
VSSA: length 46.6
  TOP w0.175: U1.12 19.85,35.25 19.1,34.5 v1(17.5,34.5) ; U2.8 23.45,36.25 24.5,35.2 v1(25.05,35.2)
  TOP w0.2: v1(17.5,34.5) C5.2 16.04,34.51 R3.1
  BOTTOM w0.175: J4.5 4,16.3 5.2,17.5 5.2,19.3 5.6,19.7 5.6,21.7 6.4,22.5 6.4,26.6 6.8,27 6.8,28.8 7.2,29.2 7.2,31 7.6,31.4 7.6,32.7 9.5,34.6 17.4,34.6 v1(17.5,34.5) 19.55,34.5 20.25,35.2 v1(25.05,35.2)
BOOT0: length 57.9
  TOP w0.175: v1(24.2,45.45) 24.2,45.2 25.25,44.15 U1.60 ; v1(26.45,37.7) 25.9,38.25 25.9,40.35 26.25,40.7 U2.44 ; v1(5.2,40) 5.2,32.9 7.4,30.7 R50.1
  TOP w0.4: S2.1 10.59,27.98 R50.1
  BOTTOM w0.175: v1(5.2,40) 5.2,42.2 5.6,42.6 5.6,44.8 7.9,47.1 23.9,47.1 24.2,46.8 v1(24.2,45.45) 24.2,44.15 25.9,42.45 25.9,38.25 v1(26.45,37.7)
EECK: length 24.2
  TOP w0.175: U3.1 25.35,64.25 26,63.6 v1(28.3,63.6)
  TOP w0.2: R9.2 25.35,50.73 U4.2 v1(29.65,50.73)
  BOTTOM w0.175: v1(29.65,50.73) 29.87,50.73 30.6,51.47 30.6,54.9 29.5,56 29.5,61.2 28.3,62.4 v1(28.3,63.6)
EECS: length 25.3
  TOP w0.2: v1(29.66,52) R10.2 25.12,52.01 U4.1 ; U3.48 v1(24.14,65.78)
  BOTTOM w0.175: v1(24.14,65.78) 25.73,65.78 27.5,64 27.5,62.6 29.1,61 29.1,55.8 30.1,54.8 30.1,52.44 v1(29.66,52)
EEDA: length 28.1
  TOP w0.175: U3.2 25.15,63.75 26.1,62.8 v1(29.2,62.8)
  TOP w0.2: R11.1 23.61,47.5 R8.2 25.58,49.47 U4.3 29.87,49.47 v1(30.7,50.3)
  BOTTOM w0.175: v1(30.7,50.3) 31.1,50.7 31.1,55 29.9,56.2 29.9,62.1 v1(29.2,62.8)
JTAG_SELN: length 4.4
  TOP w0.3: J3.27 45.4,73.35 45.4,73.91 R69.1
NRST: length 91.4
  TOP w0.175: v1(16.15,38.5) 16.4,38.25 v1(18.5,38.25) 19.05,38.25 19.55,37.75 U1.7 ; C48.1 35.9,27.2 34.1,25.4 28.5,25.4 25.2,22.1 v1(25.2,20.1) 25.2,19.31 R49.2 ; J4.10 4,28.5 8.8,23.7 11.5,23.7 v1(12.1,24.3) ; v1(25.7,36.35) 25.3,35.95 24.25,35.95 23.45,36.75 U2.7
  TOP w0.2: C48.1 S1.1 ; R42.2 v1(8.7,40.5)
  BOTTOM w0.175: v1(25.7,36.35) 25.3,35.95 22.45,35.95 20.15,38.25 v1(18.5,38.25) 17.15,38.25 15.5,36.6 8.5,36.6 5.6,33.7 5.6,32.4 5.2,32 5.2,30.2 4,29 J4.10 ; v1(12.1,24.3) 13.1,24.3 16.2,21.2 20.4,21.2 21.1,20.5 24.8,20.5 v1(25.2,20.1)
  BOTTOM w0.2: v1(16.15,38.5) 16.1,38.5 15.3,39.3 9.9,39.3 v1(8.7,40.5)
OSC32_IN: length 20.8
  TOP w0.175: v1(18.45,41.25) 18.75,41.25 20.25,39.75 U1.3 ; U2.3 23.6,38.75 v1(23.9,39.05)
  TOP w0.2: v1(18.45,41.25) 17.15,41.25 16.4,42 16.4,47 Y2.1 C4.1
  BOTTOM w0.175: v1(23.9,39.05) 22,39.05 19.8,41.25 v1(18.45,41.25)
OSC32_OUT: length 26.3
  TOP w0.175: U2.4 23.7,38.25 23.84,38.11 v1(24.45,38.11) ; U1.4 20.1,39.25 18.85,40.5 v1(17.45,40.5)
  TOP w0.2: v1(17.45,40.5) 17.2,40.5 15.9,41.8 15.9,44.1 14.9,45.1 13,45.1 12.1,46 Y2.2 C3.1
  BOTTOM w0.175: v1(24.45,38.11) 24.44,38.1 22.3,38.1 19.9,40.5 v1(17.45,40.5)
OSC_IN: length 23.2
  TOP w0.175: v1(18.5,39.78) 18.92,39.78 19.95,38.75 U1.5 ; v1(25.4,37.4) 24.05,37.4 23.7,37.75 U2.5
  TOP w0.2: Y1.2 14.49,42.21 16.92,39.78 v1(18.5,39.78)
  TOP w0.4: Y1.2 14.45,43 C1.1
  BOTTOM w0.175: v1(18.5,39.78) 19.97,39.78 22.35,37.4 v1(25.4,37.4)
OSC_OUT: length 21.3
  TOP w0.175: U1.6 19.7,38.25 18.96,38.99 v1(17.46,38.99) ; v1(24.55,36.69) 24.16,36.69 23.6,37.25 U2.6
  TOP w0.2: v1(17.46,38.99) 17.15,39.3 15.8,39.3 14.49,37.99 Y1.1
  TOP w0.4: C2.1 11.04,37.96 Y1.1
  BOTTOM w0.175: v1(17.46,38.99) 20.11,38.99 22.41,36.69 v1(24.55,36.69)
PA0: length 47
  TOP w0.175: U1.14 20.2,34.25 18.95,33 v1(17.5,33) ; U2.10 23.25,35.25 24.2,34.3 v1(24.2,33.85)
  BOTTOM w0.175: v1(24.2,33.85) 20.45,33.85 19.6,33 v1(17.5,33) 17,33 16.2,33.8 9.9,33.8 8.4,32.3 8.4,31 8,30.6 8,28.8 7.6,28.4 7.6,26.6 7.2,26.2 7.2,22.1 6.4,21.3 6.4,19.3 6,18.9 6,17.1 5.6,16.7 5.6,14.6 5.2,14.2 5.2,12.3 4,11.1 J4.3
PA1: length 67.1
  TOP w0.175: U1.15 20.3,33.75 19.7,33.15 19.7,31.8 ; 19.7,31.8 21.43,31.8 23.45,33.82 23.45,34.45 23.15,34.75 U2.11 ; 19.7,31.8 18.95,31.8 v1(18.5,32.25)
  TOP w0.2: R33.1 v1(21.3,7.3) ; J4.2 17.45,8.25 v1(18.4,7.3)
  BOTTOM w0.175: v1(18.5,32.25) 17.15,32.25 16,33.4 10.1,33.4 8.8,32.1 8.8,30.8 8.4,30.4 8.4,28.6 8,28.2 8,26.4 7.6,26 7.6,21.9 6.8,21.1 6.8,19.1 6.4,18.7 6.4,16.9 6,16.5 6,14.4 5.6,14 5.6,12.1 5.2,11.7 5.2,10 4,8.8 J4.2
  BOTTOM w0.2: v1(21.3,7.3) v1(18.4,7.3)
PA2: length 44.5
  TOP w0.3: U2.12 22.52,33.91 21.87,33.25 U1.16 v1(21.02,32.54)
  BOTTOM w0.175: J4.1 4.01,5.71 5.2,6.9 5.2,9.4 5.6,9.8 5.6,11.5 6,11.9 6,13.8 6.4,14.2 6.4,16.3 6.8,16.7 6.8,18.5 7.2,18.9 7.2,20.9 8,21.7 8,25.8 8.4,26.2 8.4,28 8.8,28.4 8.8,30.2 9.2,30.6 9.2,31.9 10.3,33 15.8,33 17.3,31.5 19.9,31.5 20.94,32.54 v1(21.02,32.54)
PA3: length 2.2
  TOP w0.175: U1.17 23.25,32.09 23.68,32.52 U2.13
PA4: length 47.3
  TOP w0.175: v1(23.4,26.2) 23.4,28.7 24.75,30.05 U1.20 U2.14 24.75,32.73
  TOP w0.2: R32.2 v1(39,23.1)
  BOTTOM w0.175: v1(23.4,26.2) 27.1,22.5 37.6,22.5 38.2,23.1 v1(39,23.1) 41.5,23.1 43.7,20.9 43.7,19.1 44.2,18.6 44.2,16.7 44.6,16.3 44.6,14.5 45,14.1 45,12.2 45.4,11.8 45.4,9.8 45.7,9.5 45.7,7 46.39,6.31 46.4,6.31 J3.1
PA5: length 45
  TOP w0.175: 25.25,32.73 U2.15 U1.21 25.25,29.95 24.2,28.9 v1(24.2,27.05)
  TOP w0.2: R31.2 v1(33,23.4)
  BOTTOM w0.175: v1(24.2,27.05) 24.2,26.3 27.5,23 30.8,23 31.2,23.4 v1(33,23.4) 34.6,23.4 35,23 37.4,23 38.3,23.9 41.3,23.9 44.1,21.1 44.1,19.3 44.6,18.8 44.6,16.9 45,16.5 45,14.7 45.4,14.3 45.4,12.4 45.8,12 45.8,10 46.9,8.9 46.9,8.35 J3.2
PA6: length 42.1
  TOP w0.175: 25.75,32.73 U2.16 U1.22 25.75,29.85 25,29.1 v1(25,27.9)
  TOP w0.2: R29.2 v1(30,23.8)
  BOTTOM w0.175: v1(25,27.9) 25,26.5 27.73,23.77 29.98,23.77 v1(30,23.8) 30.4,24.2 34.5,24.2 35.2,23.5 37.2,23.5 38,24.3 41.5,24.3 44.5,21.3 44.5,19.5 45,19 45,17.1 45.4,16.7 45.4,14.9 45.8,14.5 45.8,12.6 46.2,12.2 46.2,11.59 J3.3
PA7: length 39
  TOP w0.175: v1(25.75,28.75) 25.75,29.15 26.25,29.65 U1.23 U2.17 26.25,32.73
  TOP w0.2: v1(36.5,24.3) 36,23.8 R30.2
  BOTTOM w0.175: J3.4 46.2,14.13 46.2,14.7 45.8,15.1 45.8,16.9 45.4,17.3 45.4,19.2 44.9,19.7 44.9,21.5 41.7,24.7 37.7,24.7 37.3,24.3 v1(36.5,24.3) 35.1,24.3 34.7,24.7 27.8,24.7 25.75,26.75 v1(25.75,28.75)
PA8: length 86.4
  TOP w0.175: v1(28.05,36.01) 28.06,36.01 28.3,36.25 U2.29 ; U1.41 34.7,37.25 34.95,37.5 v1(36.15,37.5) 36.9,38.25 36.9,40.2 v1(38.7,42)
  TOP w0.2: R47.2 44.91,48.79 46,47.7 47.8,47.7 48.2,48.1 48.2,52.77 J3.20 ; Q2.1 v1(33.75,67.35)
  BOTTOM w0.175: v1(38.7,42) 39.2,42 41.1,43.9 41.1,47.5 37.8,50.8 37.8,52 37.1,52.7 37.1,64 v1(33.75,67.35) ; v1(28.05,36.01) 28.34,36.3 33.35,36.3 34.55,37.5 v1(36.15,37.5) 42.2,37.5 43.8,39.1 43.8,40.6 44.2,41 44.2,43 44.6,43.4 44.6,45.6 45,46 45,47.9 45.4,48.3 45.4,50.1 45.8,50.5 45.8,52.4 47,53.6 J3.20
PA9: length 60.8
  TOP w0.175: R59.2 37.41,63.09 38.8,61.7 44.8,61.7 46.2,60.3 47.8,60.3 48.34,59.76 48.34,57.85 J3.21 ; v1(27.15,36.75) U2.30 ; U1.42 34.6,37.75 35.1,38.25 v1(35.25,38.25)
  BOTTOM w0.175: J3.21 46.2,55.71 46.2,55 45.8,54.6 45.8,53 45.4,52.6 45.4,50.7 45,50.3 45,48.5 44.6,48.1 44.6,46.2 44.2,45.8 44.2,43.6 43.8,43.2 43.8,41.2 43.4,40.8 43.4,39.3 42.35,38.25 v1(35.25,38.25) 34.65,38.25 33.15,36.75 v1(27.15,36.75)
PA10: length 57
  TOP w0.175: U2.31 29.3,37.25 29.05,37.5 v1(28.95,37.5) ; J3.22 46.75,59.05 44.5,61.3 38.5,61.3 37.4,62.4 34.8,62.4 34.11,63.09 R34.2 ; v1(36.15,39) 34.95,39 34.2,38.25 U1.43
  BOTTOM w0.175: v1(28.95,37.5) 29.15,37.3 33.05,37.3 34.75,39 v1(36.15,39) 42.5,39 43,39.5 43,41 43.4,41.4 43.4,43.4 43.8,43.8 43.8,46 44.2,46.4 44.2,48.3 44.6,48.7 44.6,50.5 45,50.9 45,52.8 45.4,53.2 45.4,54.8 45.8,55.2 45.8,57.1 47,58.3 J3.22
PA11: length 54.3
  TOP w0.175: v1(29.95,38.05) 30.25,37.75 U2.32 ; U1.44 34.1,38.75 35.1,39.75 v1(35.25,39.75)
  TOP w0.2: U11.6 v1(42.75,62.56)
  BOTTOM w0.175: v1(29.95,38.05) 30.25,37.75 31.1,37.75 31.25,37.9 31.25,38.15 31.12,38.27 30.68,38.27 30.55,38.4 30.55,38.6 30.7,38.75 32.9,38.75 33.05,38.9 33.05,39.1 32.92,39.23 31.73,39.23 31.55,39.4 31.55,39.6 31.7,39.75 v1(35.25,39.75) 38.97,39.75 43.28,44.06 43.28,50.21 44.46,51.4 44.46,57.9 42,60.37 42,61.2 42.75,61.95 v1(42.75,62.56) 42.59,62.4 42,62.4 41.8,62.6 41.8,62.8 42.5,63.5 43.43,63.5 44.23,62.7 45.89,62.7 J3.23
PA12: length 58.8
  TOP w0.175: v1(36.15,40.46) 34.96,40.46 33.75,39.25 U1.45
  TOP w0.2: R46.2 39.11,66.39 40.1,65.4 40.1,64.8 40.85,64.05 U11.4 v1(40.85,62.56) ; U2.33 30.8,38.25 30.28,38.77 29.65,38.77 29.15,38.27 28.07,38.27 v1(27.7,37.9)
  BOTTOM w0.175: v1(27.7,37.9) 28.05,38.25 29.1,38.25 29.65,38.8 30.15,38.8 31.5,40.15 34.5,40.15 34.81,40.46 v1(36.15,40.46) 36.49,40.8 36.92,40.8 37.12,40.6 37.12,40.38 37.3,40.2 38.81,40.2 42.88,44.26 42.88,50.38 44.06,51.56 44.06,57.74 41.6,60.2 41.6,61.2 40.85,61.95 v1(40.85,62.56) 40.86,62.56 42.2,63.9 43.7,63.9 44.4,63.2 46.07,63.2 J3.24
PA13: length 51.5
  TOP w0.175: U2.34 30.85,38.75 30.05,39.55 v1(29.8,39.55) ; R36.2 43.19,48.79 42,47.6 v1(42,46.9) ; U1.46 33.65,39.75 35.1,41.2 v1(35.25,41.2)
  BOTTOM w0.175: J3.25 44.47,66.67 43.2,65.4 41.2,65.4 40,64.2 40,60.6 43.4,57.2 43.4,51.6 42,50.2 v1(42,46.9) 42,44.1 39.1,41.2 v1(35.25,41.2) 33.95,41.2 33.4,40.65 30.9,40.65 v1(29.8,39.55)
PA14: length 56.5
  TOP w0.175: v1(35.5,48.1) 36.19,48.79 R38.2 ; U1.49 30.75,41.91 30.32,41.48 U2.37
  TOP w0.2: U1.49 30.75,43.55 31,43.8 v1(31.46,43.8)
  BOTTOM w0.175: 31.46,44.6 32.7,44.6 33.4,45.3 33.4,46.66 34.84,48.1 v1(35.5,48.1) ; 31.46,44.6 31.46,45.66 31.8,46 31.8,46.9 31.5,47.2 31,47.2 29.4,48.8 28.7,48.8 26.4,51.1 8.6,51.1 6.4,53.3 6.4,57.3 5.6,58.1 5.6,60.2 5.2,60.6 5.2,62.4 4,63.6 J4.24 ; 31.46,44.6 v1(31.46,43.8)
PA15: length 67.2
  TOP w0.175: R37.2 41.69,48.79 41,48.1 40.1,48.1 39.71,47.71 38.31,47.71 37.8,47.2 v1(37.4,47.2) ; U2.38 29.25,40.89 29.59,40.55 30.25,40.55 32.3,42.6 v1(32.3,45.4) 31.9,45.4 30.25,43.75 U1.50
  BOTTOM w0.175: v1(37.4,47.2) 37.4,48 36.4,49 34.2,49 32.3,47.1 ; 32.3,47.1 v1(32.3,45.4) ; 32.3,47.1 31.7,47.7 31.1,47.7 29.6,49.2 28.9,49.2 26.6,51.5 8.8,51.5 6.8,53.5 6.8,56.1 6.79,56.11 6.79,56.69 6.8,56.7 6.8,57.5 6,58.3 6,60.4 5.6,60.8 5.6,62.6 5.2,63 5.2,65.1 4,66.3 J4.25
PB0: length 55.1
  TOP w0.175: U1.26 27.75,29.65 28,29.4 v1(28,27.85)
  TOP w0.2: v1(26.36,33.9) 26.75,33.52 U2.18 ; v1(14.6,24.8) 12.7,22.9 11.4,22.9 10.11,21.61 R64.1
  BOTTOM w0.175: 28,29.6 28,30.15 26.36,31.79 v1(26.36,33.9) ; 28,29.6 25.4,29.6 22.5,26.7 16.5,26.7 v1(14.6,24.8) ; 28,29.6 v1(28,27.85) 28,27.3 29.4,25.9 42.3,25.9 46.1,22.1 46.1,21.85 J3.7
PB1: length 42.1
  TOP w0.175: D3.C 43.9,22.3 45.09,23.49 J3.8 ; v1(28.75,28.75) 28.75,29.3 28.25,29.8 U1.27 ; U2.19 27.25,34.1 26.4,34.95 v1(26.1,34.95)
  BOTTOM w0.175: J3.8 45.31,23.49 42.5,26.3 29.8,26.3 28.75,27.35 v1(28.75,28.75) 28.75,30.15 27.2,31.7 27.2,34.2 26.45,34.95 v1(26.1,34.95)
PB2: length 63.2
  TOP w0.175: v1(27,35.6) 27,34.94 27.75,34.19 U2.20 ; U1.28 28.75,30 29.5,29.25 v1(29.5,27.85) 28.55,26.9 27.8,26.9 25.7,24.8 25.1,24.8 v1(24.3,24)
  TOP w0.3: S2.2 12,26.83 12,29 11.4,29.6 11.4,31.6 10.7,32.3 R51.1
  BOTTOM w0.175: S2.2 12.77,25.43 14.21,23.99 14.79,23.99 14.8,24 v1(24.3,24) ; v1(27,35.6) 27,34.94 27.19,34.75 27.2,34.75 27.75,34.2 27.75,31.95 29.5,30.2 v1(29.5,27.85) 29.5,27.7 30.5,26.7 42.7,26.7 43.37,26.03 J3.9
PB3: length 50.8
  TOP w0.175: R35.2 39.51,48.1 36.7,48.1 35.9,47.3 28.95,47.3 v1(28,46.35) 28,45 27.75,44.75 U1.55
  TOP w0.2: v1(28.9,40.17) 28.75,40.33 U2.39
  BOTTOM w0.175: J4.19 5.27,51.43 7.6,49.1 25.4,49.1 28,46.5 v1(28,46.35) 28,44.6 28.9,43.7 v1(28.9,40.17)
PB4: length 39.8
  TOP w0.175: v1(28.85,39.05) 28.15,39.75 28.15,40.5 28.25,40.6 U2.40 ; U1.56 v1(27.25,45.45)
  TOP w0.2: J4.18 4.01,48.9 R41.2
  BOTTOM w0.175: J4.18 4.19,48.7 25.2,48.7 27.25,46.65 v1(27.25,45.45) 27.25,44.65 28.19,43.71 28.19,39.71 v1(28.85,39.05)
PB5: length 37.9
  TOP w0.175: U1.57 26.75,44.85 26.45,45.15 v1(26.45,46.35) ; U2.41 v1(27.75,39.1)
  BOTTOM w0.175: v1(27.75,39.1) 27.75,43.3 26.45,44.6 v1(26.45,46.35) 26.45,46.65 24.8,48.3 7.3,48.3 5.35,46.35 J4.17
PB6: length 36
  TOP w0.175: v1(27,39.9) 27.25,40.15 U2.42 ; v1(25.7,45.45) 25.7,45.25 26.25,44.7 U1.58
  BOTTOM w0.175: v1(27,39.9) 27,43.15 25.7,44.45 v1(25.7,45.45) 25.7,46.7 24.5,47.9 7.5,47.9 4,44.4 J4.16
PB7: length 40.8
  TOP w0.175: U1.59 25.75,44.35 24.95,45.15 v1(24.95,46.35) ; U2.43 26.75,40.65 26.25,40.15 26.25,39.25 v1(26.7,38.8)
  BOTTOM w0.175: v1(26.7,38.8) 26.25,39.25 26.25,43 24.95,44.3 v1(24.95,46.35) 24.95,46.75 24.2,47.5 7.7,47.5 5.2,45 5.2,42.8 4,41.6 J4.15
PB8: length 40.8
  TOP w0.175: v1(25.19,38.95) 25.4,39.16 25.4,40.4 25.75,40.75 U2.45 ; v1(23.45,46.35) 23.45,45.15 24.75,43.85 U1.61
  BOTTOM w0.175: J4.14 4.07,38.8 5.3,38.8 6,39.5 6,44.6 8.1,46.7 23.1,46.7 v1(23.45,46.35) 23.45,44.1 25.4,42.15 25.4,39.16 v1(25.19,38.95)
PB9: length 38
  TOP w0.175: v1(24.6,39.85) 24.6,40.2 25.25,40.85 U2.46 ; v1(22.7,45.45) 22.7,45.3 24.25,43.75 U1.62
  BOTTOM w0.175: J4.13 4,36.7 6.4,39.1 6.4,44.4 8.3,46.3 21.85,46.3 v1(22.7,45.45) 22.7,44.05 24.6,42.15 v1(24.6,39.85)
PB10: length 28.9
  TOP w0.175: v1(28.55,33.96) 28.25,33.66 U2.21 ; v1(30.25,28.75) 30.25,29.05 29.25,30.05 U1.29
  BOTTOM w0.175: J3.10 46.97,28.57 45.5,27.1 30.7,27.1 30.25,27.55 v1(30.25,28.75) 30.25,30.15 28.55,31.85 v1(28.55,33.96)
PB11: length 32.5
  TOP w0.175: v1(31,27.85) 31,29.1 29.75,30.35 U1.30 ; U2.22 28.75,33.15 v1(29.8,34.2)
  BOTTOM w0.175: v1(31,27.85) 31,30.15 29.8,31.35 v1(29.8,34.2) 31.3,34.2 32,33.5 32,32.3 33.3,31 36.6,31 37.4,31.8 46.31,31.8 J3.11
PB12: length 63.4
  TOP w0.175: v1(42.3,19) 42.4,19 43.5,20.1 43.5,22.5 45.5,24.5 45.5,32.2 46.95,33.65 J3.12
  TOP w0.2: R61.1 v1(16.1,22.4)
  TOP w0.3: v1(32.98,32.54) U1.33 32.05,33.25 31.48,33.83 U2.25
  BOTTOM w0.175: v1(42.3,19) 41.1,19 39.2,20.9 21.5,20.9 20.8,21.6 16.9,21.6 v1(16.1,22.4) ; J3.12 43.15,33.65 41.7,32.2 37.2,32.2 36.4,31.4 34.1,31.4 32.98,32.52 v1(32.98,32.54)
PB13: length 67.8
  TOP w0.175: v1(41.5,19.8) 42.6,19.8 43.1,20.3 43.1,22.4 42.5,23 42.5,34.2 44.49,36.19 J3.13 ; U2.26 30.76,34.75 30.51,34.49 30.51,33.79 32.5,31.8 34.15,31.8 ; 34.15,31.8 34.9,31.8 v1(35.35,32.25) ; 34.15,31.8 34.15,33.25 33.65,33.75 U1.34
  TOP w0.2: R66.2 v1(20.6,22.4)
  BOTTOM w0.175: J3.13 45.09,36.19 41.5,32.6 37,32.6 36.65,32.25 v1(35.35,32.25) ; v1(20.6,22.4) 21.7,21.3 39.4,21.3 40.9,19.8 v1(41.5,19.8)
PB14: length 76.1
  TOP w0.175: v1(36.2,33) 35,33 33.75,34.25 U1.35 ; v1(28.05,34.95) 28.33,34.67 29.27,34.67 29.85,35.25 U2.27 ; J3.14 45.83,38.73 41.7,34.6 v1(41.7,21.6)
  TOP w0.2: R67.2 v1(17.6,22.4)
  BOTTOM w0.175: v1(17.6,22.4) 18.8,23.6 21.2,23.6 22.7,22.1 39.8,22.1 40.3,21.6 v1(41.7,21.6) ; J3.14 47,38.7 41.3,33 v1(36.2,33) 34.8,33 32.85,34.95 29.5,34.95 29.3,34.75 28.25,34.75 v1(28.05,34.95)
PB15: length 79.1
  TOP w0.175: U2.28 29.3,35.75 v1(29.05,35.5) ; v1(42.3,20.6) 42.5,20.8 42.5,22.4 42.1,22.8 42.1,34.4 45.2,37.5 47.7,37.5 48.3,38.1 48.3,39.97 J3.15 ; U1.36 34.15,34.75 35.15,33.75 v1(35.35,33.75)
  TOP w0.2: R65.1 v1(19.1,22.4)
  BOTTOM w0.175: J3.15 47,40.8 45.8,39.6 45.8,38.1 41.45,33.75 v1(35.35,33.75) 33.6,35.5 v1(29.05,35.5) ; v1(42.3,20.6) 40.7,20.6 39.6,21.7 22.5,21.7 21,23.2 19.9,23.2 v1(19.1,22.4)
PC0: length 25.1
  TOP w0.175: v1(17.5,37.5) 19.05,37.5 19.3,37.25 U1.8
  BOTTOM w0.175: v1(17.5,37.5) 17,37.5 15.7,36.2 8.7,36.2 6,33.5 6,32.2 5.6,31.8 5.6,30 5.2,29.6 5.2,27.8 4,26.6 J4.9
PC1: length 26.9
  TOP w0.175: U1.9 v1(18.5,36.75)
  BOTTOM w0.175: v1(18.5,36.75) 16.85,36.75 15.9,35.8 8.9,35.8 6.4,33.3 6.4,32 6,31.6 6,29.8 5.6,29.4 5.6,27.6 5.2,27.2 5.2,24.7 4.8,24.3 4.8,24.29 J4.8
PC2: length 28.8
  TOP w0.175: U1.10 19.3,36.25 19.05,36 v1(17.5,36)
  BOTTOM w0.175: v1(17.5,36) 16.7,36 16.1,35.4 9.1,35.4 6.8,33.1 6.8,31.8 6.4,31.4 6.4,29.6 6,29.2 6,27.4 5.6,27 5.6,22.9 4,21.3 J4.7
PC3: length 30.8
  TOP w0.175: U1.11 19.65,35.75 19.15,35.25 v1(18.5,35.25)
  BOTTOM w0.175: v1(18.5,35.25) 16.57,35.25 16.3,34.98 9.27,34.98 7.2,32.9 7.2,31.6 6.8,31.2 6.8,29.4 6.4,29 6.4,27.2 6,26.8 6,22.7 5.2,21.9 5.2,19.9 4,18.7 J4.6
PC4: length 31.7
  TOP w0.175: U1.24 26.75,29.4 26.5,29.15 v1(26.5,27.9)
  BOTTOM w0.175: v1(26.5,27.9) 26.5,26.9 28.3,25.1 41.9,25.1 45.3,21.7 45.3,19.9 45.8,19.4 45.8,17.5 46.2,17.1 46.2,16.67 J3.5
PC5: length 28.5
  TOP w0.175: U1.25 v1(27.25,28.75)
  BOTTOM w0.175: J3.6 46.2,19.21 46.2,19.6 45.7,20.1 45.7,21.9 42.1,25.5 28.9,25.5 27.25,27.15 v1(27.25,28.75)
PC6: length 20.5
  TOP w0.175: U1.37 34.25,35.25 35,34.5 v1(36.2,34.5)
  BOTTOM w0.175: v1(36.2,34.5) 41.6,34.5 45.4,38.3 45.4,39.8 45.8,40.2 45.8,42.2 46.2,42.6 46.2,43.01 J3.16
PC7: length 22.3
  TOP w0.175: v1(35.35,35.25) 34.9,35.25 34.4,35.75 U1.38
  BOTTOM w0.175: v1(35.35,35.25) 41.75,35.25 45,38.5 45,40 45.4,40.4 45.4,42.4 45.8,42.8 45.8,44.9 47,46.1 J3.17
PC8: length 57.7
  TOP w0.175: U1.39 34.65,36.25 34.9,36 v1(36.15,36) 36.4,36 37.8,37.4 37.8,39.9 38.2,40.3 38.9,40.3 39.3,39.9 39.3,27.6 39,27.3 36.6,27.3 34.3,25 28.9,25 27,23.1 R23.1
  BOTTOM w0.175: J3.18 47,48.7 45.8,47.5 45.8,45.6 45.4,45.2 45.4,43 45,42.6 45,40.6 44.6,40.2 44.6,38.7 41.9,36 v1(36.15,36)
PC9: length 60.3
  TOP w0.175: U1.40 v1(35.3,36.75) 36.55,36.75 37.4,37.6 37.4,40.1 38,40.7 39.1,40.7 39.7,40.1 39.7,27.4 39.2,26.9 36.8,26.9 34.5,24.6 29.3,24.6 28.5,23.8 R27.1
  BOTTOM w0.175: J3.19 47,51.1 45.8,49.9 45.8,48.1 45.4,47.7 45.4,45.8 45,45.4 45,43.2 44.6,42.8 44.6,40.8 44.2,40.4 44.2,38.9 42.05,36.75 v1(35.3,36.75)
PC10: length 75
  TOP w0.175: R28.1 40.5,25.8 41.3,26.6 41.3,44.5 39.4,46.4 37,46.4 36.58,46.82 31.52,46.82 v1(31.05,46.35) 31.05,45.2 29.75,43.9 U1.51
  BOTTOM w0.175: J4.23 4,61.2 5.2,60 5.2,57.9 6,57.1 6,53.1 8.4,50.7 26.2,50.7 28.5,48.4 29.2,48.4 31.05,46.55 v1(31.05,46.35)
PC11: length 77.5
  TOP w0.175: v1(30.25,45.45) 30.25,45.15 29.25,44.15 U1.52 ; R26.1 37.5,25 38.2,25.7 39.8,25.7 40.9,26.8 40.9,44.3 39.2,46 36.7,46 36.4,46.3 34.6,46.3 v1(34.3,46)
  BOTTOM w0.175: J4.22 4,58.5 5.6,56.9 5.6,52.9 8.2,50.3 26,50.3 28.3,48 29,48 30.25,46.75 v1(30.25,45.45) 30.25,43.85 31.1,43 31.8,43 34.3,45.5 v1(34.3,46)
PC12: length 79.4
  TOP w0.175: U1.53 28.75,44.35 29.5,45.1 v1(29.5,46.35) ; v1(37.9,44.8) 38.3,45.2 38.8,45.2 40.1,43.9 40.1,27.2 39.4,26.5 37,26.5 34.7,24.2 32.3,24.2 31.5,23.4 R25.1
  BOTTOM w0.175: J4.21 4,56 5.2,54.8 5.2,52.7 8,49.9 25.8,49.9 28.1,47.6 28.8,47.6 29.5,46.9 v1(29.5,46.35) 29.5,44.7 29.8,44.4 29.8,43.7 30.9,42.6 32.1,42.6 35.7,46.2 36.5,46.2 v1(37.9,44.8)
PC13: length 39
  TOP w0.175: U1.2 20.35,40.25 19.8,40.8 19.8,42.2 ; 19.8,42.2 v1(17.4,42.2) ; 19.8,42.2 21.55,42.2 23.43,40.33 23.43,39.58 23.1,39.25 U2.2
  BOTTOM w0.175: J4.11 4,31.4 5.2,32.6 5.2,34.7 5.6,35.1 5.6,37.1 7.2,38.7 7.2,44 8.7,45.5 16,45.5 17.4,44.1 v1(17.4,42.2)
PD2: length 73.6
  TOP w0.175: v1(28.75,45.45) 28.75,45.1 28.25,44.6 U1.54 ; R24.1 34.5,23.4 37.2,26.1 39.6,26.1 40.5,27 40.5,44.1 39,45.6 36.3,45.6 v1(36.1,45.4)
  BOTTOM w0.175: J4.20 4,53.3 7.8,49.5 25.6,49.5 27.9,47.2 28.4,47.2 28.75,46.85 v1(28.75,45.45) 28.75,44.65 29.4,44 29.4,43.5 30.7,42.2 32.4,42.2 35.6,45.4 v1(36.1,45.4)
RXD: length 8.4
  TOP w0.175: R59.1 34.51,65.7 33.5,65.7 33,65.2 32.3,65.2 30.6,66.9 29.6,66.9 29.35,66.65 U3.39
SRST: length 10.7
  TOP w0.175: U6.12 16.95,54.45 17.5,55 17.5,57.4 18.5,58.4 21.6,58.4 22.45,59.25 U3.11
SRST_OE: length 15.2
  TOP w0.175: U3.12 22.55,58.75 21.8,58 18.7,58 17.9,57.2 17.9,53.5 20,51.4 R39.2
  TOP w0.2: U6.13 17.9,53.8
TRST: length 4.2
  TOP w0.175: U3.13 23.43,57.23 22.9,56.7 22.9,56 22.65,55.75 21.62,55.75
TRST_OE: length 20.6
  TOP w0.175: U3.15 25.85,58.05 25.6,58.3 22.7,58.3 22,57.6 18.9,57.6 18.3,57 18.3,53.8 20.2,51.9 21,51.9 21.5,51.4 R40.2
  TOP w0.2: 21.62,55.1 20.6,55.1 20,54.5 18.3,54.5
TXD: length 6.1
  TOP w0.175: U3.40 28.85,64.95 29.09,64.71 R34.1
USB_CLK: length 16.5
  TOP w0.175: 37,55.7 31.2,55.7 30.35,56.55 U3.24 ; 37,55.7 37,57.6 36.2,58.4 R58.2 ; 37,55.7 38.06,55.7 40.15,57.78 U5.12
USB_TDI: length 21.1
  TOP w0.175: R57.2 44.5,59.2 43.4,60.3 42.4,60.3 42.1,60 U5.9 42.1,57.3 40.1,55.3 31,55.3 29.85,56.45 U3.23
USB_TDO: length 19.2
  TOP w0.175: R55.2 34.71,56.1 31.7,56.1 31.1,56.7 31.1,57.8 30.5,58.4 29.7,58.4 29.35,58.05 U3.22 ; v1(36.9,51.6) 37.2,51.9 39.27,51.9 39.5,52.13 U5.2
  TOP w0.2: R55.2 v1(36.2,56.9)
  BOTTOM w0.175: v1(36.2,56.9) 36.2,52.9 36.9,52.2 v1(36.9,51.6)
USB_TMS: length 19.2
  TOP w0.175: 41.45,54.65 41.2,54.9 30.3,54.9 28.85,56.35 U3.21 ; 41.45,54.65 U5.5 ; 41.45,54.65 41.5,54.6 43.2,54.6 44.31,53.49 R56.2
N50123: length 25.6
  TOP w0.175: U3.7 22.35,61.25 22,60.9 22,60.4 21.7,60.1 20.6,60.1 20.3,60.4 20.3,61.5 19.49,62.31 R13.1
  TOP w0.2: U3.7 25.15,61.25 v1(25.5,61.6) ; U12.4 v1(12.45,63.25)
  BOTTOM w0.2: v1(12.45,63.25) 13,63.8 13,64.4 13.5,64.9 16.7,64.9 20.37,61.23 23.73,61.23 24.1,61.6 v1(25.5,61.6)
N50127: length 3.8
  TOP w0.2: R4.2 23.76,67.8 C18.1 25.85,67.2 U3.46
N50535: length 1.9
  TOP w0.2: U3.20 28.35,55.56 R7.1
N50793: length 11.1
  TOP w0.2: Y3.1 27.35,72.5 U3.43
  TOP w0.4: Y3.1 27.9,73.05 C20.1
N50801: length 13.5
  TOP w0.2: Y3.2 24.46,73.04 26.85,70.65 U3.44
  TOP w0.4: Y3.2 22.8,73.05 C21.1
N51029: length 8.2
  TOP w0.6: 18.3,66 18.3,66.9 20,68.6 C10.1 ; 18.3,66 17.12,66 L1.1 D2.A ; 18.3,66 18.8,65.5 R5.1
N51243: length 3.3
  TOP w0.5: J1.1 15.1,68.5 15.62,67.97 L1.2
N51319: length 2.3
  TOP w0.2: R13.2 21.8,62.5 22.05,62.25 U3.5
N51343: length 18.8
  TOP w0.2: v1(25.5,60.3) 25.45,60.3 25,60.75 U3.8 ; U12.6 v1(14.35,63.26)
  BOTTOM w0.2: v1(14.35,63.26) 14.14,63.26 13.5,63.9 13.5,64.2 13.8,64.5 16.5,64.5 20.17,60.83 23.67,60.83 24.2,60.3 v1(25.5,60.3)
N51347: length 4.3
  TOP w0.175: U3.4 22.25,62.75 21.11,63.89 R6.1
  TOP w0.2: R5.2 R6.1
N51363: length 2.6
  TOP w0.2: C19.1 21.95,61.75 U3.6
N51511: length 3
  TOP w0.2: U4.4 25.81,48.2 R11.2
N51727: length 2
  TOP w0.6: D1.A R12.2
N70187: length 21.1
  TOP w0.2: R15.2 v1(27,10.3) 29.1,10.3 29.4,10 U10.7 ; R29.1 30,20.8 29.2,21.6 27.81,21.6 R23.2 v1(27,18.7)
  BOTTOM w0.2: v1(27,18.7) v1(27,10.3)
N70219: length 21.5
  TOP w0.2: U10.5 31.6,11.7 v1(31.5,11.8) R17.2 ; R31.1 R25.2 31.5,19.6 31.9,19.2 v1(31.9,17.4)
  BOTTOM w0.2: v1(31.5,11.8) 31.9,12.2 v1(31.9,17.4)
N70227: length 25.3
  TOP w0.2: v1(37.5,17.6) R26.2 R32.1 ; U10.2 v1(34.9,14.9) 34.8,14.8 R18.2
  BOTTOM w0.2: v1(34.9,14.9) 34.9,15 v1(37.5,17.6)
N70305: length 4
  TOP w0.2: U10.S2 28.65,17.8 R21.2
N70345: length 5.3
  TOP w0.4: U10.G2 25.26,5.05 25.21,5 ; R33.2 R22.1 25.21,5 ; 25.21,5 25.21,4.31 C47.1
N70603: length 18.6
  TOP w0.175: R27.2 28.61,20.79 v1(30.9,18.5)
  TOP w0.2: R19.2 v1(28.3,8.8) U10.8
  BOTTOM w0.2: v1(30.9,18.5) 30.9,13 28.5,10.6 28.5,9 v1(28.3,8.8)
N14914218: length 24.7
  TOP w0.175: v1(32.8,18.5) 32.8,19.2 34.39,20.79 R24.2
  TOP w0.2: U10.3 v1(33.8,13.3) R16.2 ; R24.2 R30.1
  BOTTOM w0.2: v1(33.8,13.3) 33.8,14.6 32.8,15.6 v1(32.8,18.5)
N14919452: length 2.8
  TOP w0.2: U5.3 40.15,50.46 R35.1
N14919456: length 3.2
  TOP w0.2: R36.1 43.2,50.9 42.1,52 U5.6
N14919460: length 8.8
  TOP w0.2: v1(42.5,55.5) 42.5,56.75 42.75,57 U5.8 ; R37.1 v1(41.7,51.1)
  BOTTOM w0.2: v1(41.7,51.1) 41.7,54.7 v1(42.5,55.5)
N14919464: length 9.3
  TOP w0.2: U5.11 40.8,57.4 40.78,57.38 40.78,57.28 v1(40.3,56.8) ; R38.1 v1(38.7,51.1)
  BOTTOM w0.175: v1(38.7,51.1) 38.7,55.2 v1(40.3,56.8)
N14919484: length 37.6
  TOP w0.175: v1(37.9,57.2) 38.8,57.2 39.5,57.9 U5.13 39.5,60.1 39.7,60.3 41.2,60.3 41.45,60.05 U5.10 ; U5.4 40.8,54.1 40.4,54.5 39.2,54.5 38.85,54.15 U5.1
  TOP w0.2: U5.1 v1(37.9,53.17) 37.88,53.2 R68.1
  TOP w0.3: v1(44.3,72.6) R69.2
  BOTTOM w0.175: v1(44.3,72.6) 44.3,67.1 43,65.8 40.9,65.8 39.5,64.4 39.5,58.8 v1(37.9,57.2) v1(37.9,53.17)
N14919761: length 27
  TOP w0.175: R28.2 40.5,19.1 37.7,16.3 36,16.3
  TOP w0.2: U10.1 36,16.3 R20.2
N14928576: length 23.3
  TOP w0.175: v1(7.6,54.7) 6.3,53.4 6.3,51 7.71,49.59 R41.1 7.71,47.32 R54.2
  TOP w0.2: 21.62,56.4 20.8,56.4 20.1,55.7 v1(19.2,55.7)
  BOTTOM w0.175: v1(19.2,55.7) 18.4,55.7 17.9,55.2 8.1,55.2 v1(7.6,54.7)
N14928580: length 24
  TOP w0.175: U6.11 14.8,55.1 14.4,55.5 13.45,55.5 v1(12.85,56.1) ; R42.1 8.59,43.01 6.9,44.7 6.9,49.6 5.8,50.7 5.8,54.1 v1(7.6,55.9)
  BOTTOM w0.175: v1(12.85,56.1) 12.8,56.05 12.75,56.05 12.3,55.6 7.9,55.6 v1(7.6,55.9)
N14948550: length 7.1
  TOP w0.3: L2.2 43.88,69.67 42.9,68.7 38.9,68.7 38.6,69 J2.1
N14948554: length 8.1
  TOP w0.2: U11.1 42.75,67.35 42.3,67.8 41.1,67.8 40.8,68.1 38.2,68.1 37.8,68.5 J2.2
N14948558: length 8.3
  TOP w0.2: J2.3 37,68.5 37.9,67.6 40.6,67.6 40.88,67.32 40.88,67.08 40.7,66.9 40.22,66.9 39.98,66.66 39.98,66.38 40.16,66.2 40.55,66.2 U11.3
N14952468: length 2.3
  TOP w0.2: Q1.2 38.64,65.15 37.49,66.3 R46.1
N14953185: length 11.1
  TOP w0.2: R44.2 30.61,67.79 32.1,66.3 32.77,66.3 Q2.3 32.81,66.29 R45.1 35.41,66.3 36.4,66.3 38.92,63.77 Q1.1
N14959571: length 3.5
  TOP w0.2: U12.3 12.45,67.45 13.5,68.5 J1.3
N14961045: length 3.5
  TOP w0.2: J1.2 14.3,68.6 13.74,68.04 13.74,67.76 14.35,67.15 U12.1
N14964930: length 5.3
  TOP w0.175: U1.31 30.25,30.35 30.8,29.8 31.4,29.8 32.3,28.9 C27.1
  TOP w0.2: R43.1 32.79,28.89 C27.1
N14964937: length 5.2
  TOP w0.2: U1.47 33.55,40.25 34.2,40.9 34.2,41.8 C28.1 36.59,42.7 R48.1
N14983071: length 2.7
  TOP w0.4: S2.4 18.61,27.98 R52.2
N14983075: length 2.4
  TOP w0.4: R53.2 19.18,26.01 S2.3
N14990127: length 5.4
  TOP w0.175: R62.2 11.61,19.99 12.8,18.8 12.8,16.5 U8.8
N14990147: length 6
  TOP w0.175: U8.4 18.8,16.5 18.8,18.8 19.1,19.1 19.7,19.1 20.59,19.99 R66.1
